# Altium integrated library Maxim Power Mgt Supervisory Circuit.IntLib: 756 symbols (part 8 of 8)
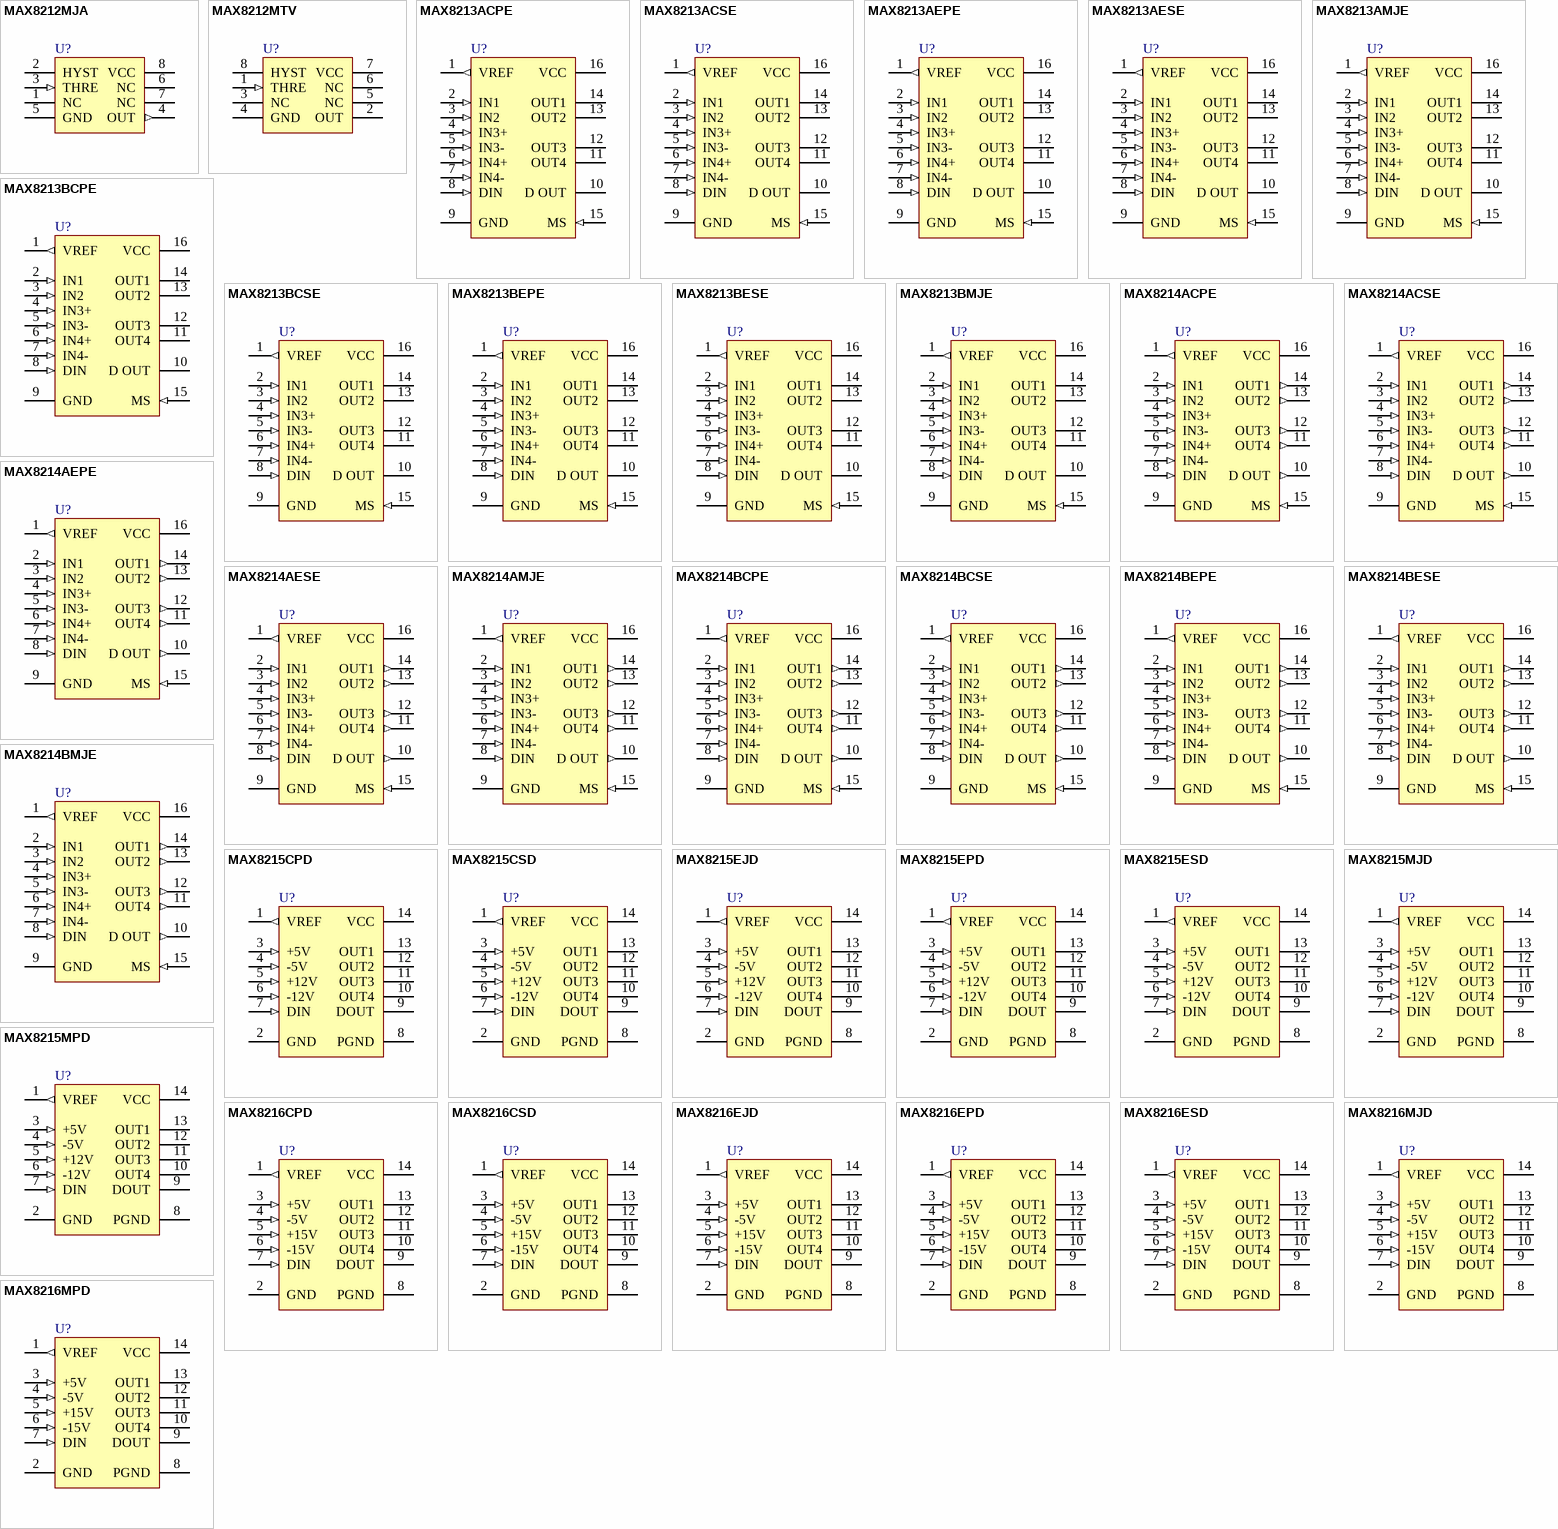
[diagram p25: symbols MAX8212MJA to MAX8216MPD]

## MAX8216MJD
designator U?
±15V Dedicated Microprocessor Voltage Monitor
footprint JD14 (DIP, 14-Leads, Row Spacing 7.62mm, Pitch 2.54mm, Body 19.56x6.73mm)
3D model JD14 (DIP, 14-Pin, Row Spacing 7.62 mm, Pitch 2.54 mm)
pins: 1 VREF (out), 2 GND (power), 3 +5V (in), 4 -5V (in), 5 +15V (in), 6 -15V (in), 7 DIN (in), 8 PGND (power), 9 DOUT (oc), 10 OUT4 (oc), 11 OUT3 (oc), 12 OUT2 (oc), 13 OUT1 (oc), 14 VCC (power)

## MAX8216MPD
designator U?
±15V Dedicated Microprocessor Voltage Monitor
footprint PD14 (DIP, 14-Leads, Row Spacing 7.62mm, Pitch 2.54mm, Body 19.05x7.24mm)
3D model PD14 (DIP, 14-Pin, Row Spacing 7.62 mm, Pitch 2.54 mm)
pins: 1 VREF (out), 2 GND (power), 3 +5V (in), 4 -5V (in), 5 +15V (in), 6 -15V (in), 7 DIN (in), 8 PGND (power), 9 DOUT (oc), 10 OUT4 (oc), 11 OUT3 (oc), 12 OUT2 (oc), 13 OUT1 (oc), 14 VCC (power)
